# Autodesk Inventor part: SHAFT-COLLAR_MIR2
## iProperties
Created: 2008-03
Part Number: SHAFT-COLLAR_MIR2
Document SubType Name: Modeling
Density: 1 g/cm^3
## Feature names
1. Derived Body1 [Tagging]
